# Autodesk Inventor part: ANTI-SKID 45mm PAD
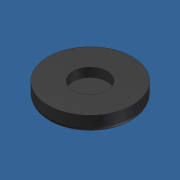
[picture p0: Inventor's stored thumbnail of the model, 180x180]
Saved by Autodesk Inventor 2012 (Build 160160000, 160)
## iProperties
Created: 2007-03
Part Number: ANTI-SKID 45mm PAD
Material: Rubber
Document SubType Name: Modeling
Designer: Andy Moles
Mass: 6.20162 g
Surface Area: 30.2508 cm^2
Volume: 6.66841 cm^3
Density: 0.93 g/cm^3
Author: Andy Moles
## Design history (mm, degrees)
sketch "Sketch1"
  geometry: C1 r 18.5 at (0, 0); 1 further point
  constraints: 1 centre point, 1 coincident
  dimensions: "d0" = 37 diameter of C1
extrude "Extrusion1" new body sketch "Sketch1" distance "d1" = 7; taper "d2" = 0 deg
sketch "Sketch2"
  geometry: C1 r 18.5 at (0, 0) reference; C2 r 7.5 at (0, 0)
  constraints: 1 centre point, 1 coincident
  dimensions: "d3" = 15 diameter of C2
extrude "Extrusion2" cut sketch "Sketch2" distance "d4" = 4; taper "d5" = 0 deg
fillet "Fillet1" dims "d6" = 2.5
body "Solid1"
